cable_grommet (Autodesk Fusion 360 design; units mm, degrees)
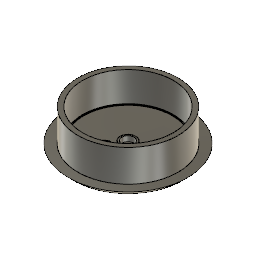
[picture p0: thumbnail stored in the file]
parameter "thickness" = 3
parameter "top_ring_outer_width" = 6 comment "How far the ring at the top should extend."
parameter "top_ring_thickness" = 3.3 comment "Thickness from the side of the ring at the top."
parameter "hole_diameter" = 63
parameter "top_ring_inner_distance" = 1.8 comment "difference of the inner groove."
parameter "groove_thickness" = 0.2
parameter "bottom_disk_thickness" = 2 comment "Thickness of the top disk that slots into the bottom part."
parameter "disk_tolerance" = 0.1
parameter "disk_hole_diameter" = 10
parameter "disk_hole_tolerance" = 0.2
parameter "top_disk_post_groove_thickness" = 0.2
parameter "top_disk_post_height" = 3.3
parameter "disk_opening_angle" = 100
parameter "disk_opening_center_width" = 5
parameter "disk_fillet" = 2
parameter "disk_bottom_groove" = 0.5 comment "Thickness of the groove on the bottom of the bottom disk to secure it in place"
parameter "disk_post_thickness" = 1
parameter "hole_depth" = 20
parameter "top_disk_tolerance" = 0.5
parameter "top_disk_end_roundness" = 2 comment "Fillet radius of the ends of the top disk"
parameter "top_disk_thickness_difference" = 0.5 comment "How much thinner the top disk should be in comparison to the bottom disk"
parameter "top_disk_post_groove_roundness" = 0.1 comment "Fillet radius of the groove along the post on the top disk"
sketch "Ring" plane through (0, 0, 0) normal (1, 0, 0) x axis (0, 1, 0)
  line L1 (28.5, 0) -> (28.5, 18.9)
  line L2 (31.5, 0) -> (28.5, 0)
  line L3 (31.5, 20) -> (31.5, 0)
  line L4 (37.5, 20) -> (31.5, 20)
  line L5 (30.4414, 23.3) -> (31.5, 23.3)
  line L6 (30.3, 23.1586) -> (30.4414, 23.3)
  line L7 (30.3, 21.3) -> (30.3, 23.1586)
  line L8 (30.1, 21.1) -> (30.3, 21.3)
  line L9 (30.3, 20.9) -> (30.1, 21.1)
  line L10 (30.3, 20.7) -> (30.3, 20.9)
  line L11 (31.5, 23.3) -> (31.5, 20)
  line L12 (34.2, 23.3) -> (31.5, 23.3)
  line L13 (37.5, 20) -> (34.2, 23.3)
  line L14 (28.5, 0) -> (0, 0)
  line L15 (0, 0) -> (0, 17.726)
  line L16 (30.3, 20.7) -> (28.5, 18.9)
  point P1 (0, 0)
  point P14 (0, 0)
  point P17 (0, 0)
  point P18 (30.3, 20.7)
  point P11 (30.3, 20.7)
  point P2 (31.5, 0)
  point P15 (28.5, 0)
  point P3 (31.5, 20)
  point P4 (37.5, 20)
  point P9 (30.1, 21.1)
  point P6 (30.4414, 23.3)
  point P7 (30.3, 23.1586)
  point P10 (30.3, 20.9)
  point P12 (28.5, 18.9)
  point P8 (30.3, 21.3)
  vertical L1
  perpendicular L1 L2
  perpendicular L2 L3
  perpendicular L3 L4
  perpendicular L3 L5
  perpendicular L5 L7
  parallel L7 L10
  perpendicular L5 L11
  collinear L7 L10
  perpendicular L11 L12
  coincident P1 P14
  horizontal L14
  vertical L15
  coincident P1 L15
  coincident P1 P17
  coincident L10 P18
  coincident P11 P18
  dimension "d14" distance P2 P15 = 3 (= "thickness")
  dimension "d15" distance P3 P4 = 6 (= "top_ring_outer_width")
  dimension "d17" distance L4 L5 = 3.3 (= "top_ring_thickness")
  dimension "d19" angle L5 L6 = 135
  dimension "d20" angle L7 L8 = 135
  dimension "d21" angle L9 L10 = 135
  dimension "d23" distance P9 L10 = 0.2 (= "groove_thickness")
  dimension "d24" distance P6 P7 = 0.2
  dimension "d28" angle L12 L13 = 135
  dimension "d29" distance P14 P15 = 28.5 (= "( hole_diameter / 2 ) - thickness")
  dimension "d31" angle L1 L16 = 135
  dimension "d33" distance P10 P12 = 2 (= "bottom_disk_thickness")
  dimension "d34" distance L1 L10 = 1.8 (= "top_ring_inner_distance")
  dimension "d35" distance L5 P8 = 2 (= "bottom_disk_thickness")
  dimension "d74" distance L2 L4 = 20 (= "hole_depth")
sketch "Bottom Disk" plane through (0, 0, 0) normal (1, 0, 0) x axis (0, 1, 0)
  line L1 (30.2, 7.3) -> (28.4, 5.5)
  line L2 (30.2, 7.5) -> (30.2, 7.3)
  line L3 (0, 7.5) -> (30.2, 7.5)
  line L4 (0, 5.5) -> (0, 7.5)
  line L5 (28.4, 5.5) -> (0, 5.5)
  line L6 (0, 0) -> (0, 17.5456)
  line L7 (5, 5.5) -> (5, 7.5)
  line L8 (28.4, 5) -> (28.4, 5.5)
  line L9 (27.9, 5) -> (28.4, 5)
  line L10 (27.9, 5.5) -> (27.9, 5)
  point P1 (0, 0)
  point P8 (0, 0)
  point P10 (5, 7.5)
  point P11 (5, 5.5)
  point P14 (27.9, 5.5)
  point P2 (28.4, 5.5)
  point P6 (0, 5.5)
  point P3 (30.2, 7.3)
  point P5 (0, 7.5)
  point P12 (28.4, 5)
  point P13 (27.9, 5)
  vertical L2
  perpendicular L2 L3
  perpendicular L3 L4
  coincident P1 P8
  parallel L4 L6
  collinear L4 L6
  coincident L3 P10
  coincident L5 P11
  perpendicular L5 L7
  perpendicular L5 L8
  perpendicular L8 L9
  coincident L5 P14
  perpendicular L5 L10
  dimension "d37" distance P2 P6 = 28.4 (= "( hole_diameter / 2 ) - thickness - disk_tolerance")
  dimension "d38" angle L1 L5 = 135
  dimension "d39" angle L1 L2 = 135
  dimension "d41" distance L3 L5 = 2 (= "bottom_disk_thickness")
  dimension "d42" distance P3 P5 = 30.2 (= "( hole_diameter / 2 ) - thickness + top_ring_inner_distance - disk_tolerance")
  dimension "d44" distance P5 L7 = 5 (= "disk_hole_diameter / 2")
  dimension "d70" distance P2 P12 = 0.5 (= "disk_bottom_groove")
  dimension "d71" distance P12 P13 = 0.5 (= "disk_bottom_groove")
sketch "Top Disk" plane through (0, 0, 0) normal (1, 0, 0) x axis (0, 1, 0)
  line L1 (0, 9.8077) -> (29.7, 9.8077)
  line L2 (0, 5.0077) -> (0, 9.8077)
  line L3 (0, 0) -> (0, 17.726)
  line L4 (4.8, 8.3077) -> (29.6921, 8.3077)
  line L5 (4.8, 5.4077) -> (4.8, 8.3077)
  line L6 (5, 5.2077) -> (4.8, 5.4077)
  line L7 (4.8, 5.0077) -> (5, 5.2077)
  line L8 (0, 5.0077) -> (4.8, 5.0077)
  line L9 (29.6921, 8.3077) -> (29.7, 9.8077)
  line L10 (4.8, 5.0077) -> (4.8, 5.4077)
  line L11 (0, 0) -> (0, 17.5456)
  line L12 (3.8, 5.0077) -> (4.8, 5.0077)
  line L13 (3.8, 8.3077) -> (3.8, 5.0077)
  line L14 (0, 8.3077) -> (3.8, 8.3077)
  point P14 (0, 5.0077)
  point P6 (0, 5.0077)
  point P17 (3.8, 5.0077)
  point P19 (0, 8.3077)
  point P2 (29.7, 9.8077)
  point P9 (29.6921, 8.3077)
  point P12 (5, 5.2077)
  point P3 (0, 9.8077)
  horizontal L1
  collinear L2 L3
  horizontal L4
  perpendicular L4 L5
  perpendicular L6 L7
  coincident L3 P14
  perpendicular L3 L8
  coincident P6 L3
  coincident P6 P14
  perpendicular L8 L10
  coincident L8 P17
  perpendicular L8 L13
  coincident L3 P19
  collinear L4 L14
  horizontal L12
  dimension "d47" distance P2 P9 = 1.5 (= "bottom_disk_thickness - top_disk_thickness_difference")
  dimension "d50" distance L4 L8 = 3.3 (= "top_disk_post_height")
  dimension "d51" angle L5 L6 = 135
  dimension "d52" distance P12 L10 = 0.2 (= "top_disk_post_groove_thickness")
  dimension "d53" distance L5 L11 = 4.8 (= "( disk_hole_diameter / 2 ) - disk_hole_tolerance")
  dimension "d54" distance P2 P3 = 29.7 (= "Linear Dimension-6")
  dimension "d73" distance L5 L13 = 1 (= "disk_post_thickness")
revolve "Revolve1" sketch "Ring" AlongAngle 360 bodies "Ring"
revolve "Revolve2" sketch "Top Disk" AlongAngle 360 bodies "Top Disk"
revolve "Revolve3" sketch "Bottom Disk" AlongAngle 360 bodies "Bottom Disk"
sketch "Disk Cutout" plane through (0, 0, 9.8077) normal (0, 0, 1) x axis (-1, 0, 0)
  line L1 (0, 0) -> (-22.7515, 19.0908)
  line L2 (22.7515, 19.0908) -> (0, 0)
  line L3 (22.7515, 19.0908) -> (-22.7515, 19.0908)
  line L4 (-23.5176, 19.7336) -> (-22.7515, 19.0908)
  line L5 (23.5176, 19.7336) -> (22.7515, 19.0908)
  circle C1 centre (0, 0) radius 29.7
  circle C2 centre (0, 0) radius 7.5
  circle C3 centre (0, 0) radius 30.7
  point P3 (-22.7515, 19.0908)
  point P4 (22.7515, 19.0908)
  point P1 (0, 0)
  point P5 (0, 0)
  point P6 (0, 0)
  point P8 (-23.5176, 19.7336)
  point P9 (23.5176, 19.7336)
  coincident C1 P3
  coincident C1 P4
  coincident P1 P5
  coincident P1 P6
  horizontal L3
  coincident C3 P8
  collinear L1 L4
  coincident C3 P9
  collinear L2 L5
  dimension "d60" angle L1 L2 = 100 (= "disk_opening_angle")
  dimension "d61" diameter C2 = 15 (= "disk_hole_diameter + disk_opening_center_width")
  dimension "d65" = 1
extrude "Extrude1" cut sketch "Disk Cutout" profile of C1 L1 L2 C2 C3 L4 L5 no distance stored
fillet "Fillet1" radius 2 (= "disk_fillet")
move "Move1"
fillet "Fillet2" radius 2 (= "top_disk_end_roundness")
move "Move2"
fillet "Fillet3" radius 0.1 (= "top_disk_post_groove_roundness")
named bodies: "Ring", "Top Disk", "Bottom Disk"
